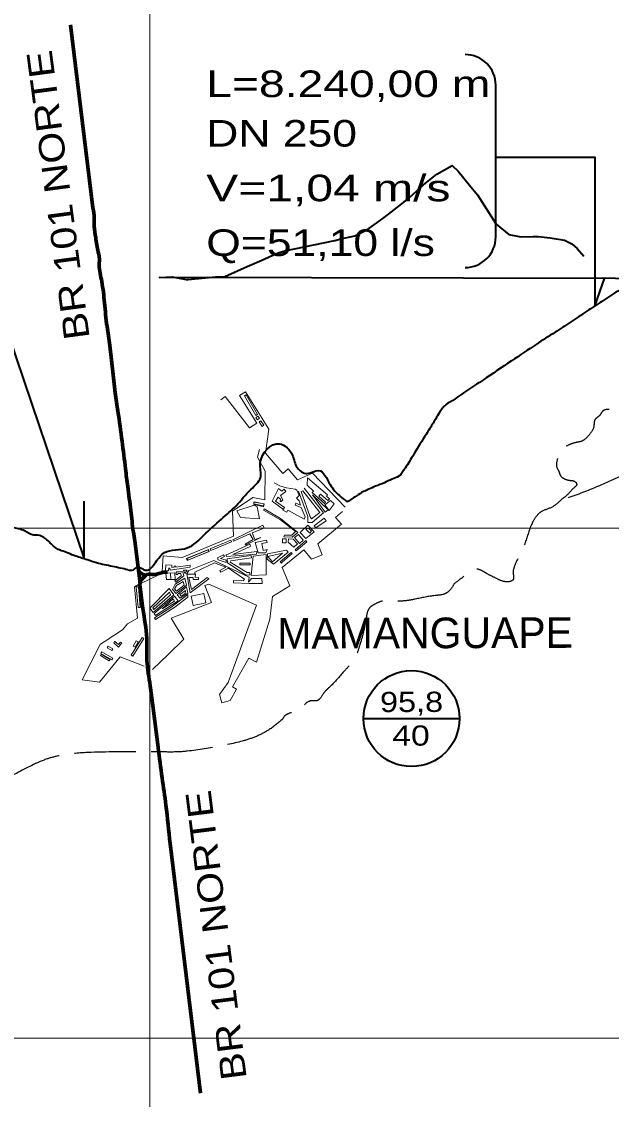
# Model space of a CAD drawing. Extents: x -4 to 42046, y -3 to 29697.
# Drawn here: x 37843 to 39683, y 13011 to 16374 of the extents above; entities that cross this region are included whole.
import ezdxf
from ezdxf.enums import TextEntityAlignment as Align

# ---------------------------------------------------------------- set-up
doc = ezdxf.new("R2010")
doc.units = 0
doc.header["$LTSCALE"] = 32
doc.linetypes.add('DOT_DASHED', pattern=[7.7, 5, -1.2, 0.3, -1.2])
doc.linetypes.add('LONG_DASHED', pattern=[7.5, 6, -1.5])
for name, color, linetype, lineweight in [('1', 7, 'DOT_DASHED', 13), ('3', 7, 'Continuous', 35), ('4', 7, 'Continuous', 13), ('5', 7, 'LONG_DASHED', 25), ('6', 7, 'Continuous', 40), ('63', 7, 'Continuous', 25), ('8', 7, 'Continuous', 35), ('9', 7, 'Continuous', 40)]:
    doc.layers.add(name, color=color, linetype=linetype, lineweight=lineweight)

msp = doc.modelspace()

# ---------------------------------------------------------------- linework, layer by layer
at = {"layer": '1', "linetype": 'Continuous'}
for p, q in [((38268.98, 14646.87), (38216.72, 14621.8)), ((38308.3, 14633.75), (38295.53, 14633.5)), ((38308.3, 14633.53), (38308.05, 14653.14))]:
    msp.add_line(p, q, dxfattribs=at)
for points in [[(38852.5, 14858.89), (38750.53, 14964.61), (38703.81, 14944.52), (38675.02, 14978.11), (38658.2, 14963.72), (38603.76, 15027.25), (38614.16, 15102.67), (38542.09, 15218.46), (38523.21, 15206.74), (38576.78, 15120.66), (38554.52, 15106.84), (38477.89, 15203.92), (38464.44, 15193.33)], [(38585.66, 15038.34), (38578.87, 15015.25), (38603.32, 14971.04), (38601.72, 14881.22), (38564.28, 14888.59), (38501.41, 14845.99), (38504.14, 14768.04), (38344.19, 14701.92), (38285, 14706.73), (38281.15, 14659.44)], [(38724.4, 14821.69), (38727.33, 14829.08), (38714.83, 14857.71), (38696.19, 14865.34), (38698.61, 14871.25), (38713.32, 14865.23), (38709.15, 14878.68), (38700.86, 14887.22), (38709.41, 14895.51), (38701.67, 14911.46), (38696.04, 14915.28), (38669.44, 14919.05), (38648.73, 14925.78), (38631.27, 14934.59)], [(38724.4, 14821.69), (38673.32, 14849.12), (38670.07, 14843.07), (38658.33, 14849.37), (38662.96, 14857.97), (38634.88, 14877.92), (38643.16, 14889.55), (38650.55, 14884.29), (38649.64, 14876.49), (38653.31, 14876.06), (38658.18, 14881.83), (38651.06, 14895.08), (38667.25, 14907.82), (38661.94, 14914.55), (38655.21, 14909.25), (38644.21, 14916.6), (38624.56, 14877.89), (38659.75, 14851.15)], [(38735.84, 14811.06), (38735.79, 14829.35), (38707.11, 14909)], [(38735.84, 14811.06), (38749.05, 14811.1), (38785.02, 14841.68), (38724.7, 14918.62)], [(38251.16, 14352.14), (38251.16, 14352.14), (38300.24, 14399.63), (38349.31, 14447.13), (38309.87, 14513.05), (38435.57, 14561.39), (38415.23, 14614.16), (38427.34, 14618.82), (38575.97, 14552.68), (38487.11, 14311.82), (38460.77, 14274.2), (38467.67, 14248.62), (38493.28, 14255.52), (38513.62, 14291.42), (38501.46, 14298.29), (38552.33, 14388.07), (38575.51, 14374.96), (38617.91, 14509.29), (38625.38, 14580.13), (38679.88, 14613.57), (38655.82, 14670.66), (38723.91, 14725.47), (38747.17, 14696.63), (38781.12, 14710.28), (38767.46, 14744.19), (38840.56, 14806.01), (38822.7, 14827.08), (38843.79, 14844.92)], [(38208.01, 14618.03), (38194.95, 14609.9), (38204.58, 14512.11), (38173.49, 14495.2), (38157.97, 14475.84), (38103.87, 14440.79), (38095.96, 14435.67), (38088.05, 14430.54), (38031.96, 14320.34), (38086.19, 14312.4), (38150.74, 14392.33), (38224.97, 14362.65)]]:
    msp.add_lwpolyline(points, dxfattribs=at)
for points in [[(38543.7, 15209.69), (38578.92, 15148.34), (38573.35, 15145.15), (38538.12, 15206.5)], [(38585.56, 15136.17), (38580.46, 15142.76), (38573.87, 15137.66), (38578.97, 15131.08)], [(38589.65, 15128.56), (38598.83, 15114.37), (38593.63, 15111.01), (38584.44, 15125.2)], [(38797.04, 14897.58), (38734.92, 14950.22), (38733.47, 14927.87), (38753.84, 14909.14), (38749.93, 14904.89), (38787.51, 14870.33), (38790.99, 14874.11), (38769.84, 14893.56), (38775.7, 14899.91), (38798.11, 14879.3), (38803.19, 14884.81), (38793.86, 14893.39)], [(38742.9, 14828.35), (38714.73, 14908.01), (38720.95, 14910.2), (38773.33, 14842.66), (38747.72, 14822.84)], [(38750.32, 14897.45), (38790.09, 14843.73), (38799.71, 14850.84)], [(38585.77, 14822.46), (38525.68, 14827.12), (38514.47, 14847.44), (38568.69, 14865.04), (38578.39, 14859.74)], [(38598.69, 14868.92), (38568.84, 14875.85), (38567.39, 14869.62), (38597.24, 14862.69)], [(38567.67, 14867.15), (38567.64, 14874.67), (38599.67, 14868.88), (38597.99, 14859.57)], [(38806.74, 14879.84), (38789.01, 14866.58), (38802.28, 14848.86), (38818.45, 14869.21)], [(38663.33, 14771.4), (38686.2, 14771.47), (38697.27, 14783.26), (38651.11, 14819.06), (38598.1, 14849.6), (38600.22, 14853.27), (38651.01, 14824), (38705.12, 14779.36), (38686.87, 14765.59), (38660.74, 14765.84)], [(38540.92, 14743.6), (38540.92, 14743.6), (38565.38, 14757.72), (38554.83, 14775.95), (38504.31, 14753.29), (38502.55, 14757.19), (38595.62, 14802.88), (38600.13, 14793.72), (38562.38, 14778.94), (38570.8, 14757.48), (38588.92, 14764.58), (38541.91, 14740.66)], [(38755.37, 14782.25), (38736.38, 14802.66), (38712.26, 14780.28), (38730.25, 14760.93)], [(38761.29, 14793.87), (38756.19, 14800.46), (38787.32, 14824.49), (38793.43, 14816.59)], [(38709.57, 14745.82), (38694.94, 14763.77), (38707.38, 14773.89), (38721.92, 14756.06)], [(38742.04, 14777.87), (38729.6, 14789.93), (38738.27, 14793.67), (38747.61, 14784.09)], [(38433.55, 14723.92), (38497.83, 14750.44), (38495.59, 14755.85), (38431.31, 14729.33)], [(38480.4, 14708.84), (38555.19, 14743.58), (38558.17, 14737.18), (38501.58, 14710.89), (38576.9, 14720.25), (38575.91, 14712.64), (38481.96, 14704.99), (38481.44, 14711.3)], [(38605.35, 14716.35), (38581.51, 14716.28), (38571.61, 14748.91), (38607.2, 14756.21), (38608.69, 14748.93), (38592.1, 14745.53), (38596.52, 14724.03), (38609.15, 14726.62)], [(38656.83, 14747.84), (38656.8, 14759.93), (38668.91, 14759.97), (38668.94, 14747.87)], [(38691.92, 14734.29), (38674.82, 14749.75), (38675.72, 14759.99), (38690.04, 14758.73), (38704.3, 14744.57)], [(38700.02, 14722.22), (38733.13, 14750.85), (38730.04, 14754.42), (38696.94, 14725.78)], [(38428.3, 14720.39), (38359.93, 14692.69), (38357.35, 14699.03), (38425.72, 14726.73)], [(38427.35, 14720.85), (38361.49, 14693.87), (38359.31, 14699.18), (38425.17, 14726.16)], [(38481.04, 14686.48), (38481.02, 14693.27), (38463.08, 14699.03), (38475.65, 14704.88), (38473.44, 14709.63), (38454.05, 14700.61), (38456.67, 14695)], [(38554.8, 14647.46), (38554.78, 14655.21), (38547.02, 14655.19), (38493.63, 14687.49), (38496.16, 14691.66), (38559.97, 14700.28), (38558.99, 14707.55), (38484.01, 14697.41), (38485.61, 14685.55), (38543.17, 14646.94)], [(38559.6, 14645.48), (38565, 14706.44), (38606.13, 14711.13), (38606.31, 14647.65)], [(38609.53, 14697.14), (38628.49, 14680.75), (38674.91, 14718.42), (38669.5, 14725.07), (38609.79, 14713.58)], [(38626.3, 14688.81), (38611.67, 14704.59), (38656.93, 14715.58)], [(38656.39, 14687.35), (38687.64, 14713.81), (38684.35, 14717.68), (38649.94, 14688.55), (38653.76, 14684.05)], [(38368.98, 14671.22), (38368.96, 14677.41), (38324.67, 14672.12), (38324.32, 14675.09), (38319.25, 14674.48), (38319.58, 14671.68), (38312.27, 14670.81), (38311.4, 14678.11), (38293.12, 14679.03), (38292.2, 14660.78), (38301.87, 14660.29), (38302.36, 14669.95), (38306.76, 14665.89), (38306.77, 14662.59)], [(38352.34, 14651.39), (38348.4, 14662.51), (38359.52, 14662.54)], [(38592.95, 14636.63), (38560.77, 14636.53), (38551.45, 14624.8), (38552.57, 14640.6), (38442.42, 14692.93), (38364.7, 14661.11), (38357.71, 14649.97), (38384.05, 14648.88), (38384.05, 14648.88), (38384.02, 14655.9), (38384.02, 14655.9), (38444.78, 14685.33), (38480.51, 14671.4), (38461.24, 14661.39), (38464.25, 14655.61), (38489.05, 14668.47), (38538.54, 14634.71), (38534.8, 14629.24), (38504.04, 14629.93), (38503.87, 14622.28), (38553.3, 14621.17), (38594.09, 14620.26)], [(38524.36, 14684.4), (38556.53, 14684.5), (38556.55, 14678.65), (38524.37, 14678.55)], [(38295.53, 14633.5), (38293.41, 14652.66), (38321.02, 14653.57), (38321.68, 14633.55)], [(38357.13, 14615.81), (38351.85, 14637.59), (38322.44, 14618.16), (38313.89, 14602.48), (38325.59, 14589.93)], [(38325.72, 14648.84), (38325.7, 14656.59), (38345.59, 14656.65), (38348.98, 14644.26), (38323.98, 14625.07), (38320.76, 14629.25), (38340.59, 14644.46), (38339.66, 14652.24), (38330.56, 14652.24), (38330.56, 14648.43), (38325.34, 14648.43)], [(38426.78, 14635.34), (38421.82, 14639.85), (38373.1, 14602.41), (38365.15, 14639.89), (38378.14, 14639.31), (38377.88, 14633.57), (38394.59, 14632.82), (38394.89, 14639.56), (38384.75, 14640.01), (38385.2, 14650.14), (38358.83, 14651.32), (38368.8, 14591.89)], [(38206.93, 14545.38), (38200.91, 14610.13), (38207.36, 14610.73), (38213.38, 14545.98)], [(38253.33, 14530.48), (38243.47, 14543.95), (38303.76, 14604.6), (38317.93, 14585.61)], [(38350.69, 14615.49), (38326.19, 14596.38), (38319.99, 14604.32), (38325.83, 14614.8), (38347.58, 14626.83)], [(38361.5, 14590.35), (38357.76, 14610.29), (38328.37, 14585.64), (38337.52, 14574.75)], [(38352.91, 14590.02), (38340.66, 14580.77), (38336.7, 14586.01), (38354.1, 14599.14)], [(38255.76, 14540), (38252.36, 14544.9), (38304.1, 14593.55), (38307.5, 14585.28)], [(38320.09, 14581.32), (38331.19, 14566.31), (38260.42, 14520.37), (38256.29, 14526.71)], [(38362.15, 14578.38), (38362.13, 14585.94), (38308.54, 14545.37), (38257.37, 14513.3), (38260.47, 14508.37), (38321.31, 14546.51)], [(38281.23, 14541.61), (38319.83, 14565.67), (38315.56, 14572.51)], [(38377.98, 14551.94), (38371.92, 14581.39), (38411.51, 14589.53), (38417.57, 14560.08)], [(38130.88, 14436), (38145.3, 14422.13), (38155.57, 14435.13), (38151.97, 14437.97), (38145.8, 14430.16), (38133.87, 14439.56)], [(38184.89, 14397.34), (38218.84, 14452.56), (38224.06, 14449.36), (38190.1, 14394.14)], [(38191.63, 14425.19), (38201.03, 14442.01), (38206.94, 14438.71), (38197.55, 14421.89)], [(38088.83, 14396.01), (38116.7, 14379.29), (38119.53, 14384), (38091.66, 14400.72)], [(38127.7, 14387.73), (38093.52, 14407.57), (38090.44, 14402.28), (38124.62, 14382.43)], [(38110.28, 14419.7), (38124.48, 14411.34), (38127.49, 14416.45), (38113.29, 14424.81)]]:
    msp.add_lwpolyline(points, close=True, dxfattribs=at)
at = {"layer": '3'}
for points in [[(41593.55, 15568.08), (38273.44, 15575.31), (38312.9, 15577), (38356.75, 15568.84), (38363.12, 15568.72), (38448.23, 15577.03), (38477.36, 15578.35), (38546.89, 15610.12), (38599.44, 15633.03), (38628.41, 15646.27), (38646.3, 15652.99), (38664.47, 15658.91), (38820.51, 15690.86), (38839, 15695.67), (38882.53, 15705.37), (38922.42, 15725.31), (38958.91, 15750.91), (38974.46, 15762.02), (39029.62, 15805.2), (39053.81, 15825.91), (39096.7, 15863.92), (39138.74, 15898.03), (39186.07, 15924.32), (39204.73, 15906.99), (39240.08, 15863.52), (39265.51, 15833.33), (39323.84, 15742.16)], [(41593.55, 15568.08), (38273.44, 15575.31), (38312.9, 15577), (38356.75, 15568.84), (38363.12, 15568.72), (38448.23, 15577.03), (38477.36, 15578.35), (38546.89, 15610.12), (38599.44, 15633.03), (38628.41, 15646.27), (38646.3, 15652.99), (38664.47, 15658.91), (38820.51, 15690.86), (38839, 15695.67), (38882.53, 15705.37), (38922.42, 15725.31), (38958.91, 15750.91), (38974.46, 15762.02), (39029.62, 15805.2), (39053.81, 15825.91), (39096.7, 15863.92), (39138.74, 15898.03), (39186.07, 15924.32), (39204.73, 15906.99), (39240.08, 15863.52), (39265.51, 15833.33), (39323.84, 15742.16)], [(39323.84, 15742.16), (39362.65, 15709.15), (39400.24, 15702.25), (39438.45, 15703.63), (39454.35, 15702.83), (39492.38, 15698.89), (39536.37, 15691.6), (39559.3, 15680.47), (39576.4, 15666.18), (39597.33, 15642.19)], [(39323.84, 15742.16), (39362.65, 15709.15), (39400.24, 15702.25), (39438.45, 15703.63), (39454.35, 15702.83), (39492.38, 15698.89), (39536.37, 15691.6), (39559.3, 15680.47), (39576.4, 15666.18), (39597.33, 15642.19)]]:
    msp.add_lwpolyline(points, dxfattribs=at)
at = {"layer": '4', "lineweight": 70}
for p, q in [((38065.74, 15793), (37995.81, 16363.65)), ((38306.18, 13809.33), (38400.96, 13030.55))]:
    msp.add_line(p, q, dxfattribs=at)
for points in [[(38212.6, 14620.63), (38204.43, 14687.31), (38196.14, 14753.62), (38191.82, 14780.98), (38183.9, 14848.83), (38174.04, 14923.23), (38167.32, 14978.35), (38156.6, 15064.71), (38143.8, 15157.92), (38135.27, 15215.65), (38126.7, 15290.09), (38118.13, 15363.13), (38109.6, 15422.96), (38101.73, 15496), (38093.18, 15562.78), (38085.37, 15614.26), (38085.3, 15639.62), (38081.87, 15654.54), (38074.41, 15699.95), (38069.92, 15734.98), (38069.85, 15760.34), (38065.74, 15793)], [(38229.97, 14645.9), (38216.12, 14652.68), (38206.76, 14660.6)], [(38306.18, 13809.33), (38293.39, 13929.18), (38281.59, 14014.41), (38268.87, 14109.4), (38252.46, 14240.02), (38244.6, 14301.89), (38234.13, 14380.63), (38233.93, 14449.68), (38221.38, 14542.23), (38212.99, 14609.22), (38212.95, 14623.71), (38216.94, 14631.82), (38228.09, 14644.19), (38234.24, 14648.45), (38255.45, 14648.52), (38287.05, 14655.55), (38298.62, 14655.59)]]:
    msp.add_spline(points, degree=3, dxfattribs=at)
at = {"layer": '5'}
for points in [[(39883.95, 15142.5), (39869.71, 15158.89), (39856.21, 15165.47), (39838.33, 15160.27), (39813.12, 15146.96), (39792.59, 15127.53), (39775.67, 15127.48), (39740.62, 15127.37), (39725.4, 15135.66), (39708.21, 15145.17), (39692.57, 15157.77), (39655.02, 15157.65), (39646.49, 15145.03), (39632.16, 15132.38), (39627.94, 15109.44), (39613.15, 15083.94), (39591.78, 15065.22), (39573.25, 15060.7), (39551.47, 15053.52), (39529.02, 15038.3), (39519.2, 15020.37), (39513.28, 15004.06), (39513.35, 14981.33), (39518.43, 14971.48), (39522.82, 14960.01), (39530.66, 14950.63), (39542.38, 14944.92), (39553.86, 14942.43), (39568.79, 14939.03), (39574.79, 14929.64), (39566.78, 14919.75), (39548.94, 14900.87), (39526.73, 14882.22)], [(39939.72, 15068.81), (39760.3, 14979.43), (39575.54, 14897.75), (39524.46, 14880.41)], [(39526.73, 14882.22), (39497.91, 14859.24), (39463.2, 14843.82), (39432.69, 14801.9), (39411.08, 14741.16), (39382.98, 14680.98), (39376.58, 14652.69), (39376.64, 14633.25), (39346.02, 14627.26), (39324.2, 14636.62), (39295.88, 14650.68), (39282.31, 14658.88), (39257.54, 14665.88), (39226.96, 14646.94), (39192.29, 14619.74)], [(39192.29, 14619.74), (39176.57, 14597.16), (39163.59, 14588.67), (39133.36, 14583.05), (39070.62, 14571.8), (39038.44, 14566.5), (39002.01, 14566.4), (38971.77, 14566.31), (38943.83, 14555.82), (38928.61, 14544.72), (38918.62, 14517.02), (38910.07, 14471.93), (38897.85, 14427.98), (38886.51, 14395.46), (38871.25, 14371.86), (38850.74, 14348.7), (38808.66, 14302.14), (38783.91, 14276.57), (38764.18, 14255.04), (38747.41, 14254.99), (38723.63, 14241.16), (38701.2, 14224.66), (38675.4, 14214.52), (38661.34, 14204.75), (38657.34, 14197.69)], [(38657.34, 14197.69), (38615.81, 14165.16), (38439.54, 14109.73), (38333.43, 14095.5), (38278.52, 14095.34), (38092.77, 14094.79), (37922.17, 14073.27), (37827.33, 14028.47), (37745.78, 14004.48), (37690.78, 14035.48), (37586.51, 14167.25), (37478.03, 14218.87), (37360.73, 14239.29), (37290.72, 14239.09), (37246.78, 14220.36), (37219.8, 14189.83), (37162.27, 14189.66), (37087.77, 14207.48), (36999.55, 14282.8), (36906.92, 14327.65), (36818.93, 14327.39), (36760.28, 14327.21), (36656.45, 14343.83), (36559.48, 14328.87), (36520.04, 14314.09), (36427.45, 14204.37)]]:
    msp.add_spline(points, degree=3, dxfattribs=at)
at = {"layer": '6'}
for points in [[(40273.96, 15670.56), (40208.64, 15643.85), (40145.69, 15604.72), (40113.58, 15588.24), (40097.16, 15582.42), (40075.13, 15578), (40047.99, 15577.92), (40007.24, 15582.01), (39969.93, 15581.89), (39895.72, 15581.67), (39837.99, 15581.5), (39799.17, 15571.76), (39749.81, 15557.78), (39703.44, 15533.09), (39653.44, 15500.84), (39606.44, 15470.15), (39555.14, 15435.73), (39507.09, 15404.55), (39448.73, 15366.82), (39371.29, 15315.2), (39280.63, 15254.37), (39206.92, 15204.91), (39181.36, 15187.93), (39164.98, 15177.13), (39156.29, 15167.72), (39146.84, 15153.73), (39134.81, 15134.78), (39127.62, 15122.36), (39105.06, 15085.78), (39066.37, 15023.76), (39039.28, 14980.22), (39030.15, 14966.68), (39026.28, 14960.3), (39019.54, 14955.37), (38998.81, 14946.28), (38974.69, 14934.84), (38946.98, 14924.24), (38926.48, 14914.89), (38909.31, 14907.25), (38887.25, 14893.63), (38872.8, 14884.41), (38858.94, 14875.56)], [(38174.6, 14663.29), (38191.8, 14663.34), (38203.05, 14671.67), (38221.59, 14665.97), (38230.62, 14661.99), (38260.85, 14686.37), (38288.75, 14716.97), (38359.75, 14731.53), (38411.29, 14771.15), (38466.39, 14821.54), (38512.19, 14863.3), (38558.68, 14914.38), (38587.99, 14950.34), (38587.85, 14997.7), (38647.22, 15056.72), (38688.23, 15020.24), (38702.59, 14982.51), (38734.29, 14963.96), (38769.38, 14973.61), (38805.93, 14929.06), (38834.64, 14894.89), (38858.81, 14875.91)], [(38174.6, 14663.29), (38127.22, 14673.83), (38076.54, 14685.21), (38047.55, 14694.39), (38012.34, 14706.01), (37988.11, 14715.31), (37967.81, 14723.05), (37954.24, 14728.92), (37942.51, 14737.58), (37932.73, 14746.93), (37918.26, 14759.96), (37893.41, 14771.8), (37880.94, 14771.76), (37852.21, 14784.5), (37814.89, 14794.46), (37801.49, 14794.42), (37781.92, 14794.36), (37763.21, 14794.3), (37758.96, 14799), (37746.47, 14810.8), (37731.41, 14819.91), (37711.64, 14827.4)]]:
    msp.add_spline(points, degree=3, dxfattribs=at)
at = {"layer": '63', "lineweight": 13}
for p, q in [((38243.06, 10019.66), (38243.06, 18929.66)), ((41110.1, 14792.87), (23907.83, 14792.87)), ((41110.1, 13201.8), (23907.83, 13201.8))]:
    msp.add_line(p, q, dxfattribs=at)
at = {"layer": '8'}
msp.add_line((39322.12, 15701.86), (39322.12, 16175.25), dxfattribs=at)
for points in [[(39322.12, 15950.52), (39630.86, 15950.52), (39630.86, 15486.12), (39662.52, 15575.18)], [(37683.5, 15742.35), (38038.84, 14697.17), (38038.84, 14877.48)]]:
    msp.add_lwpolyline(points, dxfattribs=at)
for centre, start_param, end_param in [((39226.56, 16175.25), 6.2831853, 7.8539816), ((39226.56, 16175.25), 6.2831853, 7.8539816), ((39226.56, 16175.25), 6.2831853, 7.8539816), ((39226.56, 15701.86), 4.712389, 6.2831853)]:
    msp.add_ellipse(centre, major_axis=(95.57, 0), ratio=0.998913, start_param=start_param, end_param=end_param, dxfattribs=at)
at = {"layer": '9', "lineweight": 35}
msp.add_line((38909.79, 14199.34), (39209.06, 14199.34), dxfattribs=at)
msp.add_circle((39059.43, 14199.34), 149.63, dxfattribs=at)

# ---------------------------------------------------------------- texts
at = {"layer": '8', "width": 1.2}
for rotation, p in [(97.537, (38055.9, 15386.65)), (97.135, (38545.64, 13076.84))]:
    msp.add_text('BR 101 NORTE', height=79.64, rotation=rotation, dxfattribs=at).set_placement(p)
at = {"layer": '8'}
for s, width, p in [('L=8.240,00 m', 1.3, (38419.13, 16138.18)), ('DN 250', 1.25, (38419.13, 15983.69)), ('V=1,04 m/s', 1.35, (38419.13, 15813.1)), ('Q=51,10 l/s', 1.25, (38419.13, 15642.51))]:
    msp.add_text(s, height=82.98, dxfattribs=dict(at, width=width)).set_placement(p)
at = {"layer": '9'}
msp.add_text('MAMANGUAPE', height=95.46, rotation=0.17, dxfattribs=at).set_placement((38641.04, 14417.34))
for s, width, p in [('95,8', 1.2, (39059.67, 14219.85)), ('40', 1.25, (39057.82, 14114.77))]:
    msp.add_text(s, height=63, rotation=0.17, dxfattribs=dict(at, width=width)).set_placement(p, align=Align.CENTER)

doc.saveas('drawing.dxf')
